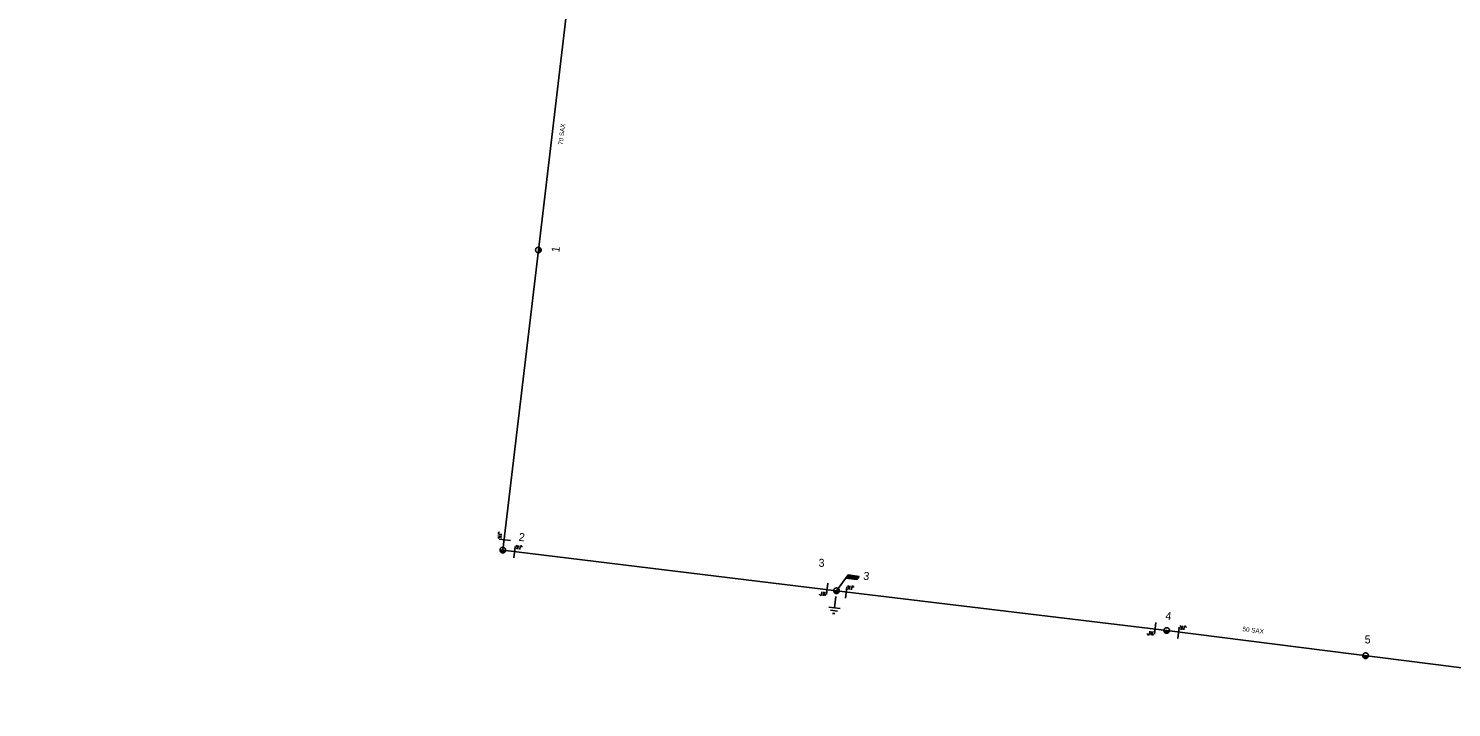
# Model space of a CAD drawing. Extents: x -540879 to -537255, y -1184046 to -1180016.
# Drawn here: x -539845.5 to -539534.4, y -1183403.8 to -1183255.4 of the extents above; entities that cross this region are included whole.
import ezdxf

# ---------------------------------------------------------------- set-up
doc = ezdxf.new("R2010")
doc.units = 0
for name, color, linetype in [('Default', 7, 'Continuous'), ('Vrstva 11', 7, 'Continuous'), ('Vrstva 12', 7, 'Continuous'), ('Vrstva 13', 7, 'Continuous'), ('Vrstva 14', 7, 'Continuous'), ('Vrstva 15', 7, 'Continuous'), ('Vrstva 18', 7, 'Continuous'), ('Vrstva 2', 7, 'Continuous'), ('Vrstva 4', 7, 'Continuous'), ('Vrstva 57', 7, 'Continuous')]:
    doc.layers.add(name, color=color, linetype=linetype)

# ---------------------------------------------------------------- blocks, each defined once
blk = doc.blocks.new('VN840')
at = {"layer": 'Vrstva 15'}
for points in [[(-0.01, 1.41), (-0.01, -1.09)], [(-1.51, -1.24), (-1.51, -1.15)], [(-1.48, -1.35), (-1.51, -1.24)], [(-1.33, -1.42), (-1.48, -1.35)], [(-1.27, -1.42), (-1.33, -1.42)], [(-1.13, -1.35), (-1.27, -1.42)], [(-1.09, -1.24), (-1.13, -1.35)], [(-1.09, -0.59), (-1.09, -1.24)], [(-0.68, -0.59), (-0.68, -1.42)], [(-0.68, -1.11), (-0.27, -0.59)], [(-0.54, -0.94), (-0.2, -1.42)]]:
    blk.add_lwpolyline(points, dxfattribs=at)
blk = doc.blocks.new('VN440')
at = {"layer": 'Vrstva 2'}
for points in [[(1.22, 0), (1.21, 0.13), (1.19, 0.25), (1.16, 0.38), (1.11, 0.5), (1.05, 0.61), (0.98, 0.72), (0.9, 0.82), (0.81, 0.91), (0.71, 0.99), (0.6, 1.06), (0.49, 1.12), (0.37, 1.16), (0.25, 1.2), (0.12, 1.22), (-0.01, 1.22), (-0.14, 1.22), (-0.26, 1.2), (-0.39, 1.16), (-0.51, 1.12), (-0.62, 1.06), (-0.73, 0.99), (-0.83, 0.91), (-0.92, 0.82), (-1, 0.72), (-1.07, 0.61), (-1.13, 0.5), (-1.18, 0.38), (-1.21, 0.25), (-1.23, 0.13), (-1.24, 0), (-1.23, -0.13), (-1.21, -0.26), (-1.18, -0.38), (-1.13, -0.5), (-1.07, -0.62), (-1, -0.73), (-0.92, -0.83), (-0.83, -0.92), (-0.73, -1), (-0.62, -1.07), (-0.51, -1.13), (-0.39, -1.17), (-0.26, -1.2), (-0.14, -1.23), (-0.01, -1.23), (0.12, -1.23), (0.25, -1.2), (0.37, -1.17), (0.49, -1.13), (0.6, -1.07), (0.71, -1), (0.81, -0.92), (0.9, -0.83), (0.98, -0.73), (1.05, -0.62), (1.11, -0.5), (1.16, -0.38), (1.19, -0.26), (1.21, -0.13), (1.22, 0)], [(-1.24, 0), (1.22, 0)], [(-1.18, -0.34), (1.1, -0.34)], [(-1.01, -0.63), (0.97, -0.63)], [(-0.74, -0.92), (0.68, -0.92)]]:
    blk.add_lwpolyline(points, dxfattribs=at)
blk = doc.blocks.new('VN810')
at = {"layer": 'Vrstva 14'}
for points in [[(0, -1.25), (0, -3.75)], [(1.25, -3.75), (-1.25, -3.75)], [(0.77, -4.37), (-0.8, -4.37)], [(0, -5), (-0.25, -5)], [(0.27, -5), (0, -5)]]:
    blk.add_lwpolyline(points, dxfattribs=at)
blk = doc.blocks.new('VN001')
at = {"layer": 'Default'}
for p, q in [((1.79, 3.13), (4.2, 3.13)), ((1.82, 3.18), (4.23, 3.18)), ((1.85, 3.23), (4.26, 3.23)), ((1.87, 3.28), (4.29, 3.28)), ((1.9, 3.33), (4.32, 3.33)), ((1.93, 3.38), (4.35, 3.38)), ((1.96, 3.43), (4.37, 3.43)), ((1.99, 3.48), (4.4, 3.48)), ((2.02, 3.53), (4.43, 3.53)), ((2.05, 3.58), (4.46, 3.58)), ((2.07, 3.63), (4.49, 3.63)), ((2.1, 3.68), (4.52, 3.68)), ((2.13, 3.73), (2.54, 3.73)), ((1.73, 3.03), (4.14, 3.03)), ((1.76, 3.08), (4.17, 3.08))]:
    blk.add_line(p, q, dxfattribs=at)
blk.add_lwpolyline([(2.13, 3.73), (0, 0)], dxfattribs=at)
blk.add_lwpolyline([(4.55, 3.73), (2.13, 3.73), (1.7, 2.98), (4.12, 2.99)], close=True, dxfattribs=at)

msp = doc.modelspace()

# ---------------------------------------------------------------- linework, layer by layer
at = {"layer": 'Vrstva 4'}
for points in [[(-539845.55, -1183204.84), (-539792.63, -1183200.68), (-539723.91, -1183218), (-539734.07, -1183303.85), (-539741.84, -1183369.42), (-539668.89, -1183378.31)], [(-539668.89, -1183378.31), (-539596.71, -1183386.99)], [(-539596.71, -1183386.99), (-539463.72, -1183403.82)]]:
    msp.add_lwpolyline(points, dxfattribs=at)

# ---------------------------------------------------------------- block references
at = {"layer": 'Vrstva 11', "rotation": -6.948049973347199}
msp.add_blockref('VN001', (-539668.89, -1183378.31), dxfattribs=at)
at = {"layer": 'Vrstva 13'}
for p, xscale, yscale, rotation in [((-539734.07, -1183303.85), 0.5, 0.5, 83.24200278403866), ((-539741.84, -1183369.42), 0.49999999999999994, 0.5000000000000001, -6.948050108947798), ((-539668.89, -1183378.31), 0.49999999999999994, 0.5, -6.857172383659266), ((-539596.71, -1183386.99), 0.5, 0.5, -6.919499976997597), ((-539553.23, -1183392.49), 0.5, 0.5, -7.2147722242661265)]:
    msp.add_blockref('VN440', p, dxfattribs=dict(at, xscale=xscale, yscale=yscale, rotation=rotation))
at = {"layer": 'Vrstva 15', "rotation": -6.948050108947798}
msp.add_blockref('VN810', (-539668.89, -1183378.31), dxfattribs=at)
at = {"layer": 'Vrstva 18'}
for p, rotation in [((-539741.57, -1183367.15), -96.75799721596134), ((-539739.3, -1183369.73), 173.0519498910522), ((-539670.94, -1183378.06), -6.948049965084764), ((-539666.8, -1183378.56), 173.1428277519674), ((-539599.27, -1183386.68), -6.857172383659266), ((-539594.13, -1183387.32), 172.7852279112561)]:
    msp.add_blockref('VN840', p, dxfattribs=dict(at, rotation=rotation))

# ---------------------------------------------------------------- texts
at = {"layer": 'Vrstva 12'}
msp.add_text('3', height=1.75, dxfattribs=at).set_placement((-539672.81, -1183373.08))
at = {"layer": 'Vrstva 14'}
for s, rotation, p in [('1', 83.242, (-539729.51, -1183304.44)), ('2', 353.052, (-539738.44, -1183367.37)), ('3', 353.143, (-539663.12, -1183375.87)), ('4', 352.75, (-539597.08, -1183384.6))]:
    msp.add_text(s, height=1.75, rotation=rotation, dxfattribs=at).set_placement(p)
msp.add_text('5', height=1.75, dxfattribs=at).set_placement((-539553.43, -1183389.82))
at = {"layer": 'Vrstva 57'}
for s, rotation, p in [('70 SAX', 83.251, (-539728.73, -1183280.92)), ('50 SAX', 352.785, (-539580.17, -1183387.13))]:
    msp.add_text(s, height=1, rotation=rotation, dxfattribs=at).set_placement(p)

doc.saveas('drawing.dxf')
